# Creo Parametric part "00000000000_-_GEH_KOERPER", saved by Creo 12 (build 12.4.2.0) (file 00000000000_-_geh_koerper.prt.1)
Units: Custom; MM, KILOGRAM, SECS

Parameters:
  PTC_WM_ITERATION = "0"
  PTC_WM_VERSION = "-.0"
  PTC_WM_LIFECYCLE_STATE = "In Work"
  PTC_WM_LIFECYCLE = "MO_CADDocument"
  PTC_WM_CREATED_BY = "Maximilian Roepper (Z0017RMS: MO)"
  PTC_WM_CREATED_ON = "18-Sep-26 11:36:42 AM"
  PTC_WM_MODIFIED_BY = "Maximilian Roepper (Z0017RMS: MO)"
  PTC_WM_MODIFIED_ON = "18-Sep-26 03:59:20 PM"
  PDMLINKNUMBER = "PDM000071455020"
  PTC_WM_NAME = "00000000000_-_geh_koerper.prt"
  PTC_WM_NUMBER = "PDM000071455020"

Other parameters: WEIGHT, WEIGHT_FACTOR, WEIGHT_ADD, _MASS_TEMP, _DIFF_TEMP, MC_ERRORS, SUPPLIER

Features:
  1. coordinate system
  2. datum plane "PRT_YZ"
  3. datum plane "PRT_XY"
  4. datum plane "PRT_XZ"
  5. datum plane "STUETZE"
  6. datum plane "STUEZTE2"
  7. coordinate system
  8. datum axis
  9. datum axis
  10. datum axis
  11. datum plane "P_BOH"
  12. datum plane "DTM1"
  13. datum plane "DTM2"
  14. datum plane "DTM3"
  15. datum axis
  16. datum axis
  17. datum axis
  18. datum axis
  19. coordinate system
  20. protrusion
  21. protrusion
  22. cut
  23. cut
  24. cut
  25. round
  26. cut
  27. round
  28. protrusion
  29. cut
  30. cut

Other named items: PRT, SIEMENS_MO, DRW_VIEW_ORG, PRT_X, PRT_Y, PRT_Z, A_BOH_1, A_BOH_2, A_BOH_3, A_BOH4, CS0, ROUGH_GROB

Layers: 00_STD_CSYS-KSYS, 01_STD_PLANES-EBENEN, 02_STD_AXES-ACHSEN, 03_STD_CSYS-KSYS, 04_PLANES-EBENEN, 05_AXES-ACHSEN, 10_ROUNDS-RUNDUNGEN, 16_CUTS-MATERIALSCHNITTE, 24_IMPORT_FEAT-IMPORT_KE

Surfaces: 36 plane, 9 cylinder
